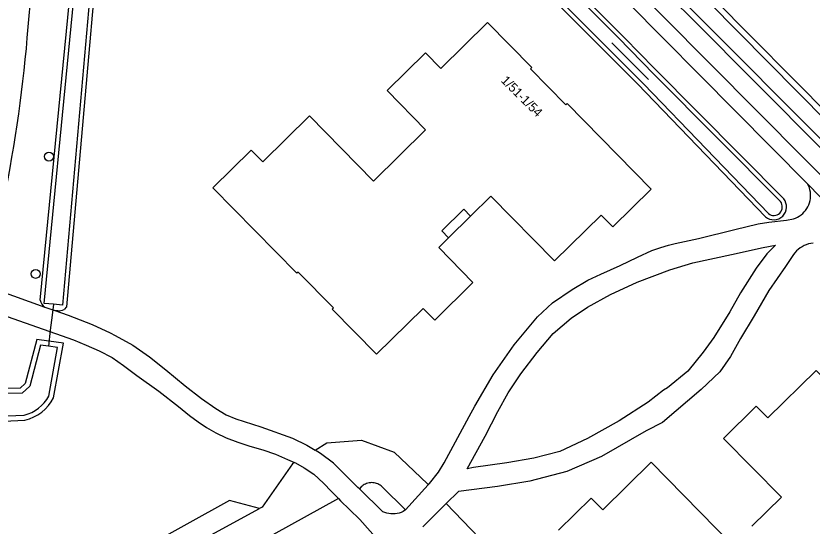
# Model space of a CAD drawing. Extents: x 162791 to 163827, y 385795 to 386523.
# Drawn here: x 162911.4 to 162998.4, y 386115 to 386170.7 of the extents above; entities that cross this region are included whole.
import ezdxf

# ---------------------------------------------------------------- set-up
doc = ezdxf.new("R2010")
doc.units = 0
for name, color, linetype in [('IMGEO_Boom', 7, 'Continuous'), ('IMGEO_Duiker', 7, 'Continuous'), ('IMGEO_Erf', 7, 'Continuous'), ('IMGEO_Fietspad_gesloten', 7, 'Continuous'), ('IMGEO_Groenvoorziening', 7, 'Continuous'), ('IMGEO_Pand', 7, 'Continuous'), ('IMGEO_Pand_nummerreeks', 7, 'Continuous'), ('IMGEO_Pand_overbouw', 7, 'Continuous'), ('IMGEO_Parkeervlak_open', 7, 'Continuous'), ('IMGEO_Waterloop', 7, 'Continuous'), ('IMGEO_Woonerf_gesloten', 7, 'Continuous'), ('IMGEO_Woonerf_open', 7, 'Continuous')]:
    doc.layers.add(name, color=color, linetype=linetype)

msp = doc.modelspace()

# ---------------------------------------------------------------- linework, layer by layer
at = {"layer": 'IMGEO_Boom'}
for centre in [(162914.965, 386155.331), (162913.508, 386142.519)]:
    msp.add_circle(centre, 0.489, dxfattribs=at)
at = {"layer": 'IMGEO_Duiker'}
for points in [[(162980.499, 386163.74), (162979.583, 386164.657), (162977.5, 386166.744), (162976.48, 386167.766)], [(162915.467, 386139.203), (162915.321, 386138.017)], [(162915.321, 386138.017), (162915.117, 386136.369), (162914.899, 386134.612)]]:
    msp.add_lwpolyline(points, dxfattribs=at)
at = {"layer": 'IMGEO_Erf'}
for points in [[(162939.283, 386206.783), (162977.871, 386168.299), (162981.132, 386164.949), (162995.272, 386150.715)], [(162993.272, 386148.756), (162979.304, 386163.275), (162975.879, 386166.678), (162937.722, 386204.727)], [(162914.007, 386139.632), (162919.895, 386199.943)], [(162922.25, 386199.745), (162916.882, 386138.911), (162916.619, 386138.631)], [(163009.646, 386150.318), (163005.787, 386149.75), (162999.516, 386156.061), (162985.265, 386170.371), (162983.184, 386172.461), (162980.008, 386175.65), (162979.797, 386176.339), (162980.054, 386176.979), (162980.589, 386177.518), (162981.556, 386178.158), (162982.352, 386177.855), (162985.467, 386174.749), (162987.558, 386172.662), (163000.485, 386159.606), (163009.646, 386150.318)], [(162915.923, 386138.488), (162915.62, 386138.511)]]:
    msp.add_lwpolyline(points, dxfattribs=at)
for centre, radius, start, end in [((162994.17, 386149.839), 1.407, 230.33795, 38.47537), ((162915.222, 386139.939), 1.254, 194.19457, 236.09318), ((162916.052, 386139.625), 1.145, 263.52625, 299.69456)]:
    msp.add_arc(centre, radius, start, end, dxfattribs=at)
at = {"layer": 'IMGEO_Fietspad_gesloten'}
for centre, radius, start, end in [((162663.897, 386194.175), 250, 354.60918, 358.99126), ((162753.908, 386182.068), 159.29, 349.0237, 355.90309)]:
    msp.add_arc(centre, radius, start, end, dxfattribs=at)
at = {"layer": 'IMGEO_Groenvoorziening'}
for points in [[(162915.479, 386128.992), (162916.553, 386134.935), (162914.967, 386135.157), (162913.643, 386135.344), (162912.375, 386130.56), (162911.806, 386130.048), (162908.596, 386129.978)], [(162909.237, 386126.409), (162912.342, 386126.549)]]:
    msp.add_lwpolyline(points, dxfattribs=at)
msp.add_arc((162911.274, 386131.156), 4.729, 283.05087, 332.76987, dxfattribs=at)
at = {"layer": 'IMGEO_Pand'}
for points in [[(162943.434, 386159.772), (162950.426, 386152.658), (162956.132, 386158.266), (162951.929, 386162.541), (162956.116, 386166.656), (162957.791, 386164.951), (162962.89, 386169.963), (162967.723, 386165.046), (162967.583, 386164.908), (162971.443, 386160.981), (162971.583, 386161.119), (162980.762, 386151.78), (162976.576, 386147.665), (162975.321, 386148.942), (162970.222, 386143.93), (162963.265, 386151.008), (162961.047, 386148.828), (162960.3, 386149.588), (162957.896, 386147.226), (162958.643, 386146.466), (162957.559, 386145.4), (162961.306, 386141.588), (162957.12, 386137.474), (162955.865, 386138.75), (162950.766, 386133.738), (162945.933, 386138.656), (162946.073, 386138.794), (162942.213, 386142.72), (162942.073, 386142.582), (162932.894, 386151.921), (162937.08, 386156.036), (162938.335, 386154.76), (162943.434, 386159.772)], [(162991.783, 386114.948), (162995.007, 386118.116), (162988.691, 386124.542), (162992.271, 386128.061), (162993.526, 386126.784), (162998.804, 386131.971), (163005.895, 386124.757), (163007.488, 386126.323), (163012.159, 386121.57), (163010.566, 386120.004), (163020.251, 386110.151)], [(162970.65, 386114.508), (162974.231, 386118.026), (162975.485, 386116.75), (162980.763, 386121.937), (162989.672, 386112.873)]]:
    msp.add_lwpolyline(points, dxfattribs=at)
at = {"layer": 'IMGEO_Pand_overbouw'}
msp.add_lwpolyline([(162961.047, 386148.828), (162960.3, 386149.588), (162957.896, 386147.226), (162958.643, 386146.466)], close=True, dxfattribs=at)
at = {"layer": 'IMGEO_Parkeervlak_open'}
for points in [[(162937.968, 386116.9), (162934.709, 386117.77), (162925.052, 386112.426), (162924.209, 386109.405)], [(162924.209, 386109.405), (162937.968, 386116.9)]]:
    msp.add_lwpolyline(points, dxfattribs=at)
at = {"layer": 'IMGEO_Waterloop'}
for points in [[(162938.966, 386206.444), (162977.179, 386168.334), (162981.117, 386164.306), (162994.923, 386150.408)], [(162993.586, 386149.098), (162979.968, 386163.254), (162975.91, 386167.302), (162938.03, 386205.075)], [(162916.434, 386139.114), (162915.467, 386139.203), (162914.44, 386139.297), (162920.357, 386199.899)], [(162921.788, 386199.784), (162916.434, 386139.114)], [(162984.985, 386174.266), (162987.075, 386172.181), (163000, 386159.127), (163008.216, 386150.797), (163006.028, 386150.475), (163000, 386156.542), (162985.748, 386170.852), (162983.667, 386172.942), (162980.611, 386176.011), (162980.52, 386176.308), (162980.636, 386176.597), (162981.024, 386176.988), (162981.64, 386177.396), (162981.973, 386177.269), (162984.985, 386174.266)], [(162914.953, 386129.173), (162915.911, 386134.47), (162914.899, 386134.612), (162914.049, 386134.732), (162912.864, 386130.261), (162912.022, 386129.503), (162908.604, 386129.429)], [(162909.527, 386126.969), (162912.265, 386127.096)]]:
    msp.add_lwpolyline(points, dxfattribs=at)
for centre, radius, start, end in [((162994.17, 386149.839), 0.944, 231.78042, 37.05076), ((162911.277, 386131.153), 4.176, 283.69176, 331.6943)]:
    msp.add_arc(centre, radius, start, end, dxfattribs=at)
at = {"layer": 'IMGEO_Woonerf_gesloten'}
for points in [[(162956.41, 386119.477), (162956.541, 386119.621), (162957.548, 386120.872), (162958.165, 386121.886), (162960.89, 386126.928), (162961.511, 386128.065), (162963.512, 386131.509), (162965.795, 386134.771), (162968.346, 386137.829), (162970.009, 386139.37), (162972.145, 386140.802), (162973.846, 386141.84), (162975.274, 386142.479), (162977.379, 386143.434), (162979.277, 386144.36), (162980.859, 386145.078), (162981.83, 386145.408), (162982.686, 386145.64), (162983.416, 386145.82), (162985.937, 386146.372), (162989.924, 386147.353), (162992.461, 386147.975), (162993.654, 386148.161), (162995.579, 386148.383), (162996.324, 386148.534), (162996.547, 386148.612), (162996.762, 386148.709), (162996.967, 386148.825), (162997.161, 386148.958), (162997.343, 386149.109), (162997.51, 386149.275), (162997.662, 386149.455), (162997.797, 386149.648), (162997.915, 386149.852), (162998.014, 386150.066), (162998.093, 386150.288), (162998.152, 386150.516), (162998.191, 386150.748), (162998.209, 386150.983), (162998.206, 386151.219), (162998.182, 386151.453), (162998.137, 386151.684), (162998.072, 386151.911), (162997.987, 386152.131), (162997.883, 386152.342)], [(163004.756, 386145.273), (162997.883, 386152.342)], [(162998.479, 386145.875), (162998.224, 386145.839), (162997.973, 386145.782), (162997.729, 386145.703), (162997.491, 386145.604), (162997.264, 386145.484), (162997.047, 386145.346), (162996.843, 386145.19), (162996.653, 386145.016), (162996.479, 386144.827), (162996.321, 386144.624), (162996.182, 386144.408), (162995.475, 386143.316), (162993.635, 386140.715), (162992.041, 386137.943), (162990.561, 386135.442), (162989.443, 386133.511), (162988.278, 386131.817), (162986.243, 386129.883), (162982.036, 386126.272), (162980.221, 386125.364), (162975.363, 386122.564), (162971.552, 386120.921), (162967.504, 386119.884), (162963.982, 386119.288), (162959.726, 386118.753), (162958.387, 386117.423)], [(162977.292, 386126.478), (162973.828, 386124.527), (162970.782, 386123.122), (162967.975, 386122.405), (162965.022, 386121.886), (162961.37, 386121.372), (162960.688, 386121.239), (162962.654, 386124.792), (162964.014, 386127.473), (162965.16, 386129.542), (162966.529, 386131.582), (162968.319, 386133.934), (162970.069, 386135.991), (162972.023, 386137.676), (162973.818, 386138.868), (162976.345, 386140.278), (162979.237, 386141.614), (162982.821, 386142.947), (162985.345, 386143.708), (162989.572, 386144.617), (162993.015, 386145.409), (162994.366, 386145.647), (162993.418, 386144.705), (162992.264, 386143.125), (162990.554, 386140.447), (162989.369, 386138.371), (162987.623, 386135.567), (162986.46, 386133.983), (162984.805, 386131.896), (162982.559, 386130.073), (162982.125, 386129.799), (162980.456, 386128.507), (162977.292, 386126.478)], [(162907.626, 386141.34), (162914.523, 386138.899)], [(162907.038, 386139.04), (162917.651, 386135.301), (162919.047, 386134.74), (162920.457, 386134.113), (162921.884, 386133.389), (162923.095, 386132.52), (162924.576, 386131.407), (162926.963, 386129.719), (162929.136, 386128.035), (162930.323, 386127.058), (162931.258, 386126.364), (162932.193, 386125.733), (162933.2, 386125.156), (162934.318, 386124.625), (162935.611, 386124.121), (162936.914, 386123.713), (162938.346, 386123.314), (162939.713, 386122.825), (162941.036, 386122.261), (162941.794, 386121.92)], [(162914.523, 386138.899), (162915.62, 386138.511)], [(162915.62, 386138.511), (162917.072, 386137.997), (162919.68, 386136.98), (162921.639, 386136.077), (162922.186, 386135.782), (162924.117, 386134.738), (162924.141, 386134.722), (162925.963, 386133.474), (162927.757, 386132.047), (162929.851, 386130.286), (162931.634, 386128.903), (162933.211, 386127.82), (162934.34, 386127.14), (162935.391, 386126.675), (162938.137, 386125.815), (162941.591, 386124.583), (162943.166, 386123.814), (162944.046, 386123.271)], [(162948.895, 386119.032), (162948.721, 386119.201), (162946.052, 386121.83), (162944.658, 386122.893), (162944.046, 386123.271)], [(162941.794, 386121.92), (162941.906, 386121.869), (162942.841, 386121.345), (162943.91, 386120.646), (162944.961, 386119.642), (162945.834, 386118.733), (162946.592, 386117.975)], [(162953.927, 386116.757), (162953.681, 386116.561), (162953.471, 386116.47), (162953.254, 386116.398), (162953.031, 386116.344), (162952.804, 386116.311), (162952.576, 386116.298), (162952.347, 386116.305), (162952.119, 386116.332), (162951.895, 386116.379), (162951.676, 386116.446), (162951.464, 386116.532), (162948.895, 386119.032)], [(162956.41, 386119.477), (162953.927, 386116.757)], [(162946.592, 386117.975), (162946.824, 386117.743), (162947.799, 386116.794), (162948.954, 386115.694), (162950.921, 386113.462), (162949.063, 386111.524), (162946.028, 386108.902), (162943.236, 386106.606), (162940.24, 386104.343), (162937.761, 386102.46), (162935.592, 386101.258), (162932.958, 386100.213), (162929.787, 386099.112), (162926.598, 386098.081), (162923.82, 386096.946), (162921.428, 386095.97), (162917.363, 386094.344), (162915.522, 386093.594), (162913.7, 386092.561), (162912.191, 386091.347), (162910.59, 386089.723)], [(162955.829, 386114.882), (162958.387, 386117.423)]]:
    msp.add_lwpolyline(points, dxfattribs=at)
at = {"layer": 'IMGEO_Woonerf_open'}
for points in [[(162997.883, 386152.342), (162970.367, 386180.135), (162937.328, 386213.523)], [(163013.888, 386204.203), (163005.124, 386195.909), (163001.751, 386191.657), (162991.499, 386185.046), (162983.201, 386179.878), (162976.869, 386175.895), (163002.732, 386149.828)], [(162944.046, 386123.271), (162945.348, 386124.052), (162949.122, 386124.354), (162952.696, 386123.045), (162956.32, 386119.571), (162956.41, 386119.477)], [(162941.794, 386121.92), (162941.573, 386121.787), (162938.251, 386117.054), (162937.968, 386116.9)], [(162953.927, 386116.757), (162951.367, 386119.269), (162951.262, 386119.361), (162951.149, 386119.442), (162951.03, 386119.514), (162950.906, 386119.576), (162950.776, 386119.627), (162950.643, 386119.667), (162950.506, 386119.695), (162950.368, 386119.711), (162950.229, 386119.716), (162950.09, 386119.709), (162949.953, 386119.69), (162949.817, 386119.659), (162949.684, 386119.617), (162949.556, 386119.564), (162949.432, 386119.501), (162949.314, 386119.426), (162949.203, 386119.343), (162949.1, 386119.25), (162948.895, 386119.032)], [(162946.592, 386117.975), (162939.45, 386114.029)], [(162958.387, 386117.423), (162965.639, 386109.891), (162991.633, 386083.508)]]:
    msp.add_lwpolyline(points, dxfattribs=at)

# ---------------------------------------------------------------- texts
at = {"layer": 'IMGEO_Pand_nummerreeks'}
msp.add_text('1/51-1/54', height=1, rotation=315.15098, dxfattribs=at).set_placement((162964.292, 386163.559))

doc.saveas('drawing.dxf')
